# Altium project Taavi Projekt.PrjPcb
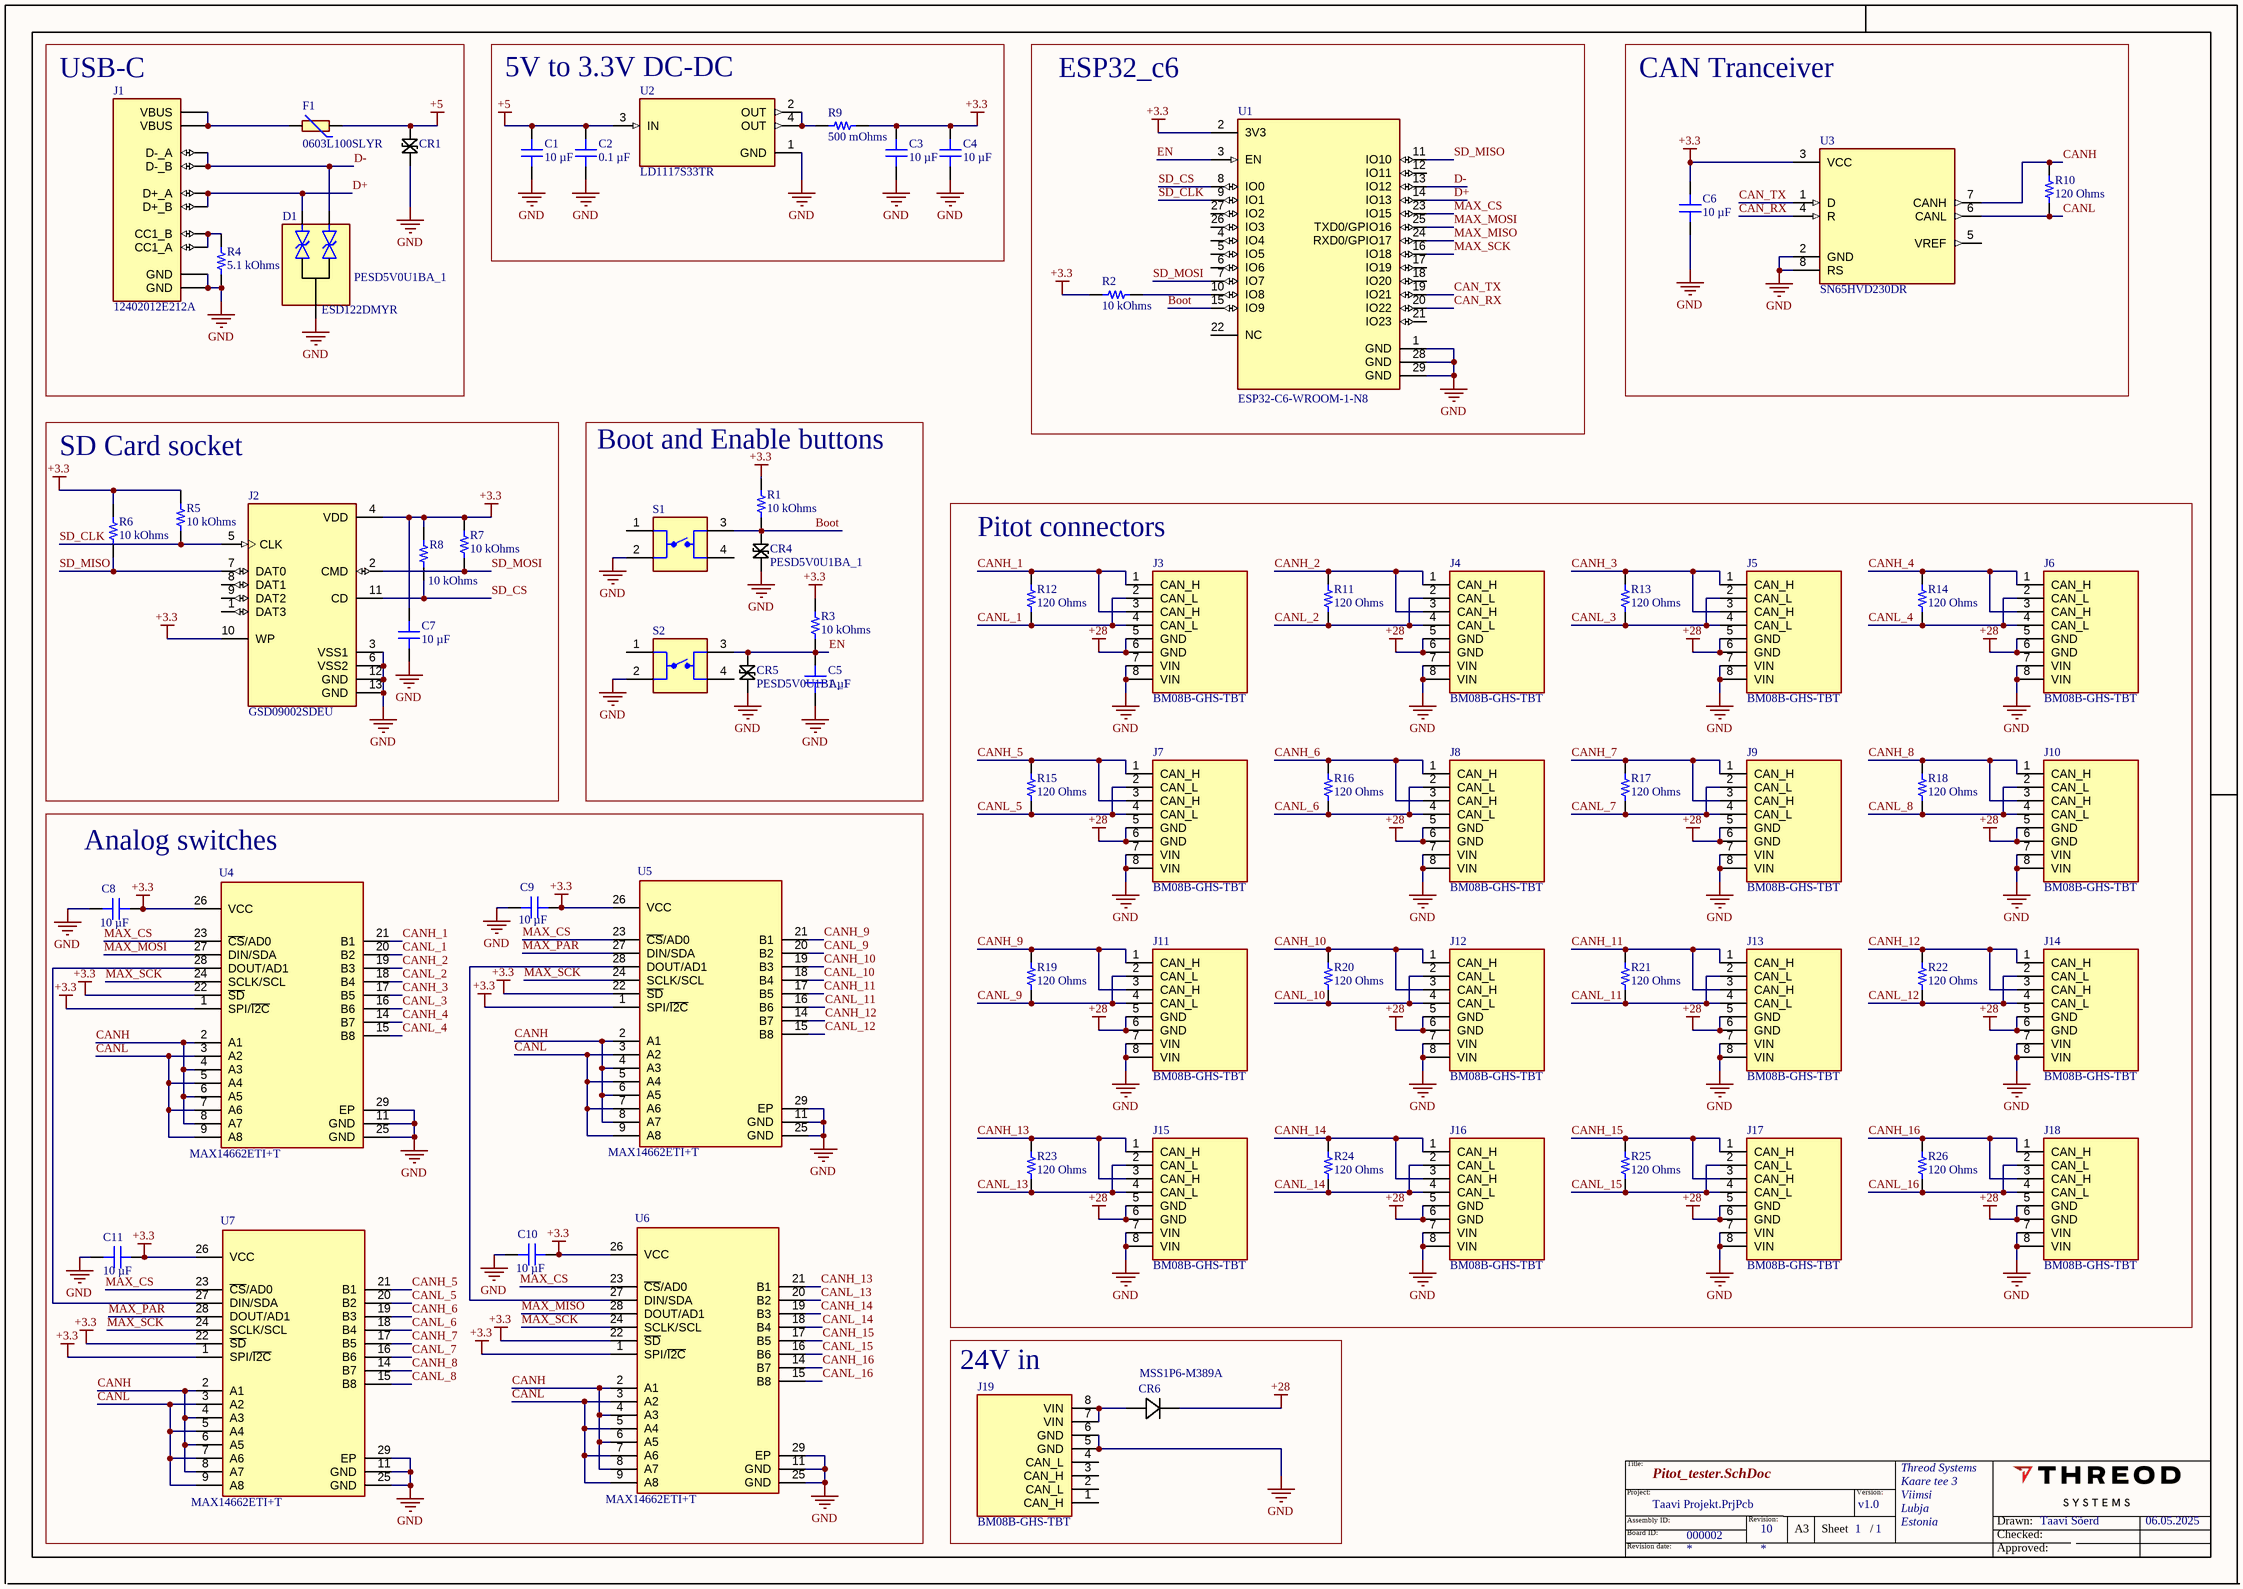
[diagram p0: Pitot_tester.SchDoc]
ThBoardID: 000002; ThBoardname: Pitot-tester; ThDrawn: Taavi Sõerd; ThDrawnDate: 06.05.2025; ThProduct: XXX; ThRevision: 10; ThRouted: Router Name; ThVersion: v1.0
1 sheet, 71 parts. Net scope: global (net labels, ports and power ports of the same name join across sheets).
Board files: Pitot_tester.PcbDoc, ProjectName_Panel.PcbDoc

## Sheet Pitot_tester.SchDoc
size 420 x 297 mm; SheetNumber: 1; SheetTotal: 1

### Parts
C1  10 µF  [MURATA GRM188 0603_1608]
C2  0.1 µF  [CAP 0603_1608]
C3  10 µF  [CAP 1206_3216 - 0.8MM]
C4  10 µF  [CAP 1206_3216 - 0.8MM]
C5  1 µF  [CAP 0603_1608]
C6  10 µF  [CAP 1206_3216 - 0.8MM]
C7  10 µF  [CAP 1206_3216 - 0.8MM]
C8  10 µF  [CAP 1206_3216 - 0.8MM]
C9  10 µF  [CAP 1206_3216 - 0.8MM]
C10  10 µF  [CAP 1206_3216 - 0.8MM]
C11  10 µF  [CAP 1206_3216 - 0.8MM]
CR1  PESD5V0U1BA_1  [SOD323_NXP]
CR4  PESD5V0U1BA_1  [SOD323_NXP]
CR5  PESD5V0U1BA_1  [SOD323_NXP]
CR6  MSS1P6-M389A  [DIODE_MSP3V3_VIS]
D1  ESD122DMYR  [DIO_ESD122DMYR]
F1  0603L100SLYR  [FUSC1608X100N]
J1  12402012E212A  [AMPHENOL_12402012E212A]
J2  GSD09002SDEU  [AMPHENOL_GSD09002SDEU]
J3  BM08B-GHS-TBT  [CONN_BM08B-GHS-TBT_JST]
J4  BM08B-GHS-TBT  [CONN_BM08B-GHS-TBT_JST]
J5  BM08B-GHS-TBT  [CONN_BM08B-GHS-TBT_JST]
J6  BM08B-GHS-TBT  [CONN_BM08B-GHS-TBT_JST]
J7  BM08B-GHS-TBT  [CONN_BM08B-GHS-TBT_JST]
J8  BM08B-GHS-TBT  [CONN_BM08B-GHS-TBT_JST]
J9  BM08B-GHS-TBT  [CONN_BM08B-GHS-TBT_JST]
J10  BM08B-GHS-TBT  [CONN_BM08B-GHS-TBT_JST]
J11  BM08B-GHS-TBT  [CONN_BM08B-GHS-TBT_JST]
J12  BM08B-GHS-TBT  [CONN_BM08B-GHS-TBT_JST]
J13  BM08B-GHS-TBT  [CONN_BM08B-GHS-TBT_JST]
J14  BM08B-GHS-TBT  [CONN_BM08B-GHS-TBT_JST]
J15  BM08B-GHS-TBT  [CONN_BM08B-GHS-TBT_JST]
J16  BM08B-GHS-TBT  [CONN_BM08B-GHS-TBT_JST]
J17  BM08B-GHS-TBT  [CONN_BM08B-GHS-TBT_JST]
J18  BM08B-GHS-TBT  [CONN_BM08B-GHS-TBT_JST]
J19  BM08B-GHS-TBT  [CONN_BM08B-GHS-TBT_JST]
R1  10 kOhms  [YAGEO RES 0603_1608]
R2  10 kOhms  [YAGEO RES 0603_1608]
R3  10 kOhms  [YAGEO RES 0603_1608]
R4  5.1 kOhms  [RES 0603_1608]
R5  10 kOhms  [YAGEO RES 0603_1608]
R6  10 kOhms  [YAGEO RES 0603_1608]
R7  10 kOhms  [YAGEO RES 0603_1608]
R8  10 kOhms  [YAGEO RES 0603_1608]
R9  500 mOhms  [RES 1206_3216]
R10  120 Ohms  [YAGEO RES 0603_1608]
R11  120 Ohms  [YAGEO RES 0603_1608]
R12  120 Ohms  [YAGEO RES 0603_1608]
R13  120 Ohms  [YAGEO RES 0603_1608]
R14  120 Ohms  [YAGEO RES 0603_1608]
R15  120 Ohms  [YAGEO RES 0603_1608]
R16  120 Ohms  [YAGEO RES 0603_1608]
R17  120 Ohms  [YAGEO RES 0603_1608]
R18  120 Ohms  [YAGEO RES 0603_1608]
R19  120 Ohms  [YAGEO RES 0603_1608]
R20  120 Ohms  [YAGEO RES 0603_1608]
R21  120 Ohms  [YAGEO RES 0603_1608]
R22  120 Ohms  [YAGEO RES 0603_1608]
R23  120 Ohms  [YAGEO RES 0603_1608]
R24  120 Ohms  [YAGEO RES 0603_1608]
R25  120 Ohms  [YAGEO RES 0603_1608]
R26  120 Ohms  [YAGEO RES 0603_1608]
S1  PTS525SM15SMTR2LFS  [SW_PTS525SM15SMTR2LFS]  (value not drawn)
S2  PTS525SM15SMTR2LFS  [SW_PTS525SM15SMTR2LFS]  (value not drawn)
U1  ESP32-C6-WROOM-1-N8  [XCVR_ESP32-C6-WROOM-1-N8]
U2  LD1117S33TR  [SOT230P700X180-4N]
U3  SN65HVD230DR  [SOIC127P599X175-8N]
U4  MAX14662ETI+T  [21-0139I_T2844-1C_MXM]
U5  MAX14662ETI+T  [21-0139I_T2844-1C_MXM]
U6  MAX14662ETI+T  [21-0139I_T2844-1C_MXM]
U7  MAX14662ETI+T  [21-0139I_T2844-1C_MXM]

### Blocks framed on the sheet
USB-C: CR1 D1 F1 J1 R4
5V to 3.3V DC-DC: C1-C4 R9 U2
ESP32_c6: R2 U1
CAN Tranceiver: C6 R10 U3
SD Card socket: C7 J2 R5-R8
Boot and Enable buttons: C5 CR4 CR5 R1 R3 S1 S2
Pitot connectors: J3-J18 R11-R26
Analog switches: C8-C11 U4-U7
24V in: CR6 J19

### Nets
+3.3: C3.2 C4.2 C6.2 C7.2 C8.1 C9.1 C10.1 C11.1 J2.4(VDD) J2.10(WP) R1.2 R2.1 R3.2 R5.2 R6.2 R7.2 R8.2 R9.2 U1.2(3V3) U3.3(VCC) U4.1(SPI/~{I2C}) U4.22(~{SD}) U4.26(VCC) U5.1(SPI/~{I2C}) U5.22(~{SD}) U5.26(VCC) U6.1(SPI/~{I2C}) U6.22(~{SD}) U6.26(VCC) U7.1(SPI/~{I2C}) U7.22(~{SD}) U7.26(VCC)
+5: C1.2 C2.2 CR1.2 F1.1 U2.3(IN)
+28: CR6.1 J3.5(GND) J3.6(GND) J4.5(GND) J4.6(GND) J5.5(GND) J5.6(GND) J6.5(GND) J6.6(GND) J7.5(GND) J7.6(GND) J8.5(GND) J8.6(GND) J9.5(GND) J9.6(GND) J10.5(GND) J10.6(GND) J11.5(GND) J11.6(GND) J12.5(GND) J12.6(GND) J13.5(GND) J13.6(GND) J14.5(GND) J14.6(GND) J15.5(GND) J15.6(GND) J16.5(GND) J16.6(GND) J17.5(GND) J17.6(GND) J18.5(GND) J18.6(GND)
GND: C1.1 C2.1 C3.1 C4.1 C5.2 C6.1 C7.1 C8.2 C9.2 C10.2 C11.2 CR1.1 CR4.1 CR5.1 D1.1(GND) J1.A1_B12(GND) J1.B1_A12(GND) J2.3(VSS1) J2.6(VSS2) J2.12(GND) J2.13(GND) J3.7(VIN) J3.8(VIN) J4.7(VIN) J4.8(VIN) J5.7(VIN) J5.8(VIN) J6.7(VIN) J6.8(VIN) J7.7(VIN) J7.8(VIN) J8.7(VIN) J8.8(VIN) J9.7(VIN) J9.8(VIN) J10.7(VIN) J10.8(VIN) J11.7(VIN) J11.8(VIN) J12.7(VIN) J12.8(VIN) J13.7(VIN) J13.8(VIN) J14.7(VIN) J14.8(VIN) J15.7(VIN) J15.8(VIN) J16.7(VIN) J16.8(VIN) J17.7(VIN) J17.8(VIN) J18.7(VIN) J18.8(VIN) J19.5(GND) J19.6(GND) R4.2 S1.2 S2.2 U1.1(GND) U1.28(GND) U1.29(GND) U2.1(GND) U3.2(GND) U3.8(RS) U4.11(GND) U4.25(GND) U4.29(EP) U5.11(GND) U5.25(GND) U5.29(EP) U6.11(GND) U6.25(GND) U6.29(EP) U7.11(GND) U7.25(GND) U7.29(EP)
Boot: CR4.2 R1.1 S1.3 U1.15(IO9)
CAN_RX: U1.20(IO22) U3.4(R)
CAN_TX: U1.19(IO21) U3.1(D)
CANH: R10.2 U3.7(CANH) U4.2(A1) U4.4(A3) U4.6(A5) U4.8(A7) U5.2(A1) U5.4(A3) U5.6(A5) U5.8(A7) U6.2(A1) U6.4(A3) U6.6(A5) U6.8(A7) U7.2(A1) U7.4(A3) U7.6(A5) U7.8(A7)
CANH_1: J3.1(CAN_H) J3.3(CAN_H) R12.2 U4.21(B1)
CANH_2: J4.1(CAN_H) J4.3(CAN_H) R11.2 U4.19(B3)
CANH_3: J5.1(CAN_H) J5.3(CAN_H) R13.2 U4.17(B5)
CANH_4: J6.1(CAN_H) J6.3(CAN_H) R14.2 U4.14(B7)
CANH_5: J7.1(CAN_H) J7.3(CAN_H) R15.2 U7.21(B1)
CANH_6: J8.1(CAN_H) J8.3(CAN_H) R16.2 U7.19(B3)
CANH_7: J9.1(CAN_H) J9.3(CAN_H) R17.2 U7.17(B5)
CANH_8: J10.1(CAN_H) J10.3(CAN_H) R18.2 U7.14(B7)
CANH_9: J11.1(CAN_H) J11.3(CAN_H) R19.2 U5.21(B1)
CANH_10: J12.1(CAN_H) J12.3(CAN_H) R20.2 U5.19(B3)
CANH_11: J13.1(CAN_H) J13.3(CAN_H) R21.2 U5.17(B5)
CANH_12: J14.1(CAN_H) J14.3(CAN_H) R22.2 U5.14(B7)
CANH_13: J15.1(CAN_H) J15.3(CAN_H) R23.2 U6.21(B1)
CANH_14: J16.1(CAN_H) J16.3(CAN_H) R24.2 U6.19(B3)
CANH_15: J17.1(CAN_H) J17.3(CAN_H) R25.2 U6.17(B5)
CANH_16: J18.1(CAN_H) J18.3(CAN_H) R26.2 U6.14(B7)
CANL: R10.1 U3.6(CANL) U4.3(A2) U4.5(A4) U4.7(A6) U4.9(A8) U5.3(A2) U5.5(A4) U5.7(A6) U5.9(A8) U6.3(A2) U6.5(A4) U6.7(A6) U6.9(A8) U7.3(A2) U7.5(A4) U7.7(A6) U7.9(A8)
CANL_1: J3.2(CAN_L) J3.4(CAN_L) R12.1 U4.20(B2)
CANL_2: J4.2(CAN_L) J4.4(CAN_L) R11.1 U4.18(B4)
CANL_3: J5.2(CAN_L) J5.4(CAN_L) R13.1 U4.16(B6)
CANL_4: J6.2(CAN_L) J6.4(CAN_L) R14.1 U4.15(B8)
CANL_5: J7.2(CAN_L) J7.4(CAN_L) R15.1 U7.20(B2)
CANL_6: J8.2(CAN_L) J8.4(CAN_L) R16.1 U7.18(B4)
CANL_7: J9.2(CAN_L) J9.4(CAN_L) R17.1 U7.16(B6)
CANL_8: J10.2(CAN_L) J10.4(CAN_L) R18.1 U7.15(B8)
CANL_9: J11.2(CAN_L) J11.4(CAN_L) R19.1 U5.20(B2)
CANL_10: J12.2(CAN_L) J12.4(CAN_L) R20.1 U5.18(B4)
CANL_11: J13.2(CAN_L) J13.4(CAN_L) R21.1 U5.16(B6)
CANL_12: J14.2(CAN_L) J14.4(CAN_L) R22.1 U5.15(B8)
CANL_13: J15.2(CAN_L) J15.4(CAN_L) R23.1 U6.20(B2)
CANL_14: J16.2(CAN_L) J16.4(CAN_L) R24.1 U6.18(B4)
CANL_15: J17.2(CAN_L) J17.4(CAN_L) R25.1 U6.16(B6)
CANL_16: J18.2(CAN_L) J18.4(CAN_L) R26.1 U6.15(B8)
D+: D1.3(IO2) J1.A6(D+_A) J1.B6(D+_B) U1.14(IO13)
D-: D1.2(IO1) J1.A7(D-_A) J1.B7(D-_B) U1.13(IO12)
EN: C5.1 CR5.2 R3.1 S2.3 U1.3(EN)
MAX_CS: U1.23(IO15) U4.23(~{CS}/AD0) U5.23(~{CS}/AD0) U6.23(~{CS}/AD0) U7.23(~{CS}/AD0)
MAX_MISO: U1.24(RXD0/GPIO17) U6.28(DOUT/AD1)
MAX_MOSI: U1.25(TXD0/GPIO16) U4.27(DIN/SDA)
MAX_PAR: U5.27(DIN/SDA) U7.28(DOUT/AD1)
MAX_SCK: U1.16(IO18) U4.24(SCLK/SCL) U5.24(SCLK/SCL) U6.24(SCLK/SCL) U7.24(SCLK/SCL)
SD_CLK: J2.5(CLK) R5.1 U1.9(IO1)
SD_CS: J2.11(CD) R8.1 U1.8(IO0)
SD_MISO: J2.7(DAT0) R6.1 U1.11(IO10)
SD_MOSI: J2.2(CMD) R7.1 U1.7(IO7)
NetCR6_2: CR6.2 J19.7(VIN) J19.8(VIN)
NetF1_2: F1.2 J1.A4_B9(VBUS) J1.B4_A9(VBUS)
NetJ1_A5: J1.A5(CC1_A) J1.B5(CC1_B) R4.1
NetR2_2: R2.2 U1.10(IO8)
NetR9_1: R9.1 U2.2(OUT) U2.4(OUT)
NetU4_28: U4.28(DOUT/AD1) U7.27(DIN/SDA)
NetU5_28: U5.28(DOUT/AD1) U6.27(DIN/SDA)

Not connected (* = marked no-connect by the designer): J2 1(DAT3) 8(DAT1) 9(DAT2); J19 1(CAN_H) 2(CAN_L) 3(CAN_H) 4(CAN_L); S1 1 4; S2 1 4; U1 4(IO4) 5(IO5) 6(IO6) 12(IO11) 17(IO19) 18(IO20) 21(IO23) 22(NC) 26(IO3) 27(IO2); U3 5(VREF)

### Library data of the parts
C1 = GRM188R60J106ME47D: CAP CER 10UF 6.3V X5R 0603; manufacturer: Murata Electronics; Tolerance: ±20%
C2 = 6R3X14W104MV4T: CAP CER 0.1UF 6.3V X7R 0603; manufacturer: Johanson Dielectrics Inc.; Tolerance: ±20%
C3 C4 C6-C11 = EMK316BJ106MD-T: CAP CER 10UF 16V X5R 1206; manufacturer: Taiyo Yuden; Tolerance: ±20%
C5 = C0603C105K4RACAUTO: CAP CER 1UF 16V X7R 0603; manufacturer: KEMET; Tolerance: ±10%
CR1 CR4 CR5 = PESD5V0U1BA_1: No Description Available; Mfr_Name: NXP
CR6 = MSS1P6-M389A: No Description Available; Mfr_Name: Vishay
D1 = ESD122DMYR: Dual 0.2-pF, Â±3.6-V, Â±17-kV ESD protection diode for USB Type-C and HDMI 2.0; MF: Texas Instruments
J1 = 12402012E212A: USB2.0, Type C, Top mount, CH 1.68mm, Dual Row SMT; MF: Amphenol ICC (Commercial Products)
J2 = GSD09002SDEU: Micro SD and SD Card Sockets, Input Output Connectors, SD Socket,9Position Push Push 15Î¼in Gold; MF: Amphenol Commercial Products
J3-J19 = BM08B-GHS-TBT: No Description Available; Mfr_Name: JST
R1-R3 R5-R8 = RT0603DRD0710KL: RES SMD 10K OHM 0.5% 1/10W 0603; Manufacturer: Yageo; Power (Watts): 0.1W, 1/10W; Temperature Coefficient: ±25ppm/°C
R4 = TNPW06035K10BYEN: RES 5.1K OHM 0.1% 1/10W 0603; Manufacturer: Vishay Dale; Power (Watts): 0.125W, 1/8W; Temperature Coefficient: ±10ppm/°C
R9 = CSR1206FTR500: RES 0.5 OHM 1% 1/2W 1206; Manufacturer: Stackpole Electronics Inc; Power (Watts): 0.5W, 1/2W; Temperature Coefficient: ±100ppm/°C
R10-R26 = AC0603JR-07120RL: RES SMD 120 OHM 5% 1/10W 0603; Manufacturer: Yageo; Power (Watts): 0.1W, 1/10W; Temperature Coefficient: ±100ppm/°C
S1 S2 = PTS525SM15SMTR2LFS: Tactile Switch SPST-NO Top Actuated Surface Mount; MF: C&K
U1 = ESP32-C6-WROOM-1-N8: Multiprotocol Modules ESP32-C6 module, Wi-Fi 6 in 2.4 GHz band, Bluetooth 5, Zigbee 3.0 and Thread. ESP34-WROOM Compatible - ENGINEERING SAMPLE; MF: Espressif Systems
U2 = LD1117S33TR: Linear Voltage Regulator IC Positive Fixed 1 Output 800mA SOT-223; MF: STMicroelectronics
U3 = SN65HVD230DR: 3.3 V CAN Transceiver with Standby Mode; MF: Texas Instruments
U4-U7 = MAX14662ETI+T: No Description Available; Mfr_Name: Analog Devices / Maxim Integrated

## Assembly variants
000001: all parts fitted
